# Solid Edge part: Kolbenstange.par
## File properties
Username: ahadarics
Dokumentum tartalom típus: 0
Author: ahadarics
Last saved by: ahadarics
Revision: 79
Sűrűség: 0,000 kg/m^3
Pontosság: 0,990
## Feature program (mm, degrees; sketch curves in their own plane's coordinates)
base feature "unnamed BaseFeature 1"
sketch for "unnamed Protrusion 1" plane through (90.5, 0, 0) normal (1, 0, 0) x-axis (0, 1, 0)
  circle centre (0, 0) radius 50
extrude "unnamed Protrusion 1" add finite 28 along -normal
thread "unnamed Thread 1"
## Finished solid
Body 1: solid body, 17 faces, 23 edges, 8 vertices.
  Faces by surface: plane 8, cylinder 4, torus 3, cone 2
  Edges by curve: circle 13, line 6, ellipse 2, intersection 2
Bounding box of the edges (mm; curved faces can reach further): 105.500 x 100.000 x 100.000, from (-15, -50, -50) to (90.5, 50, 50).
Cylindrical faces by radius (mm): R7 x1, R8 x1, R12.5 x1, R50 x1
Conical faces (half-angle, radius in mm at the cone's reference point): 20 deg R7.4 x1, 60 deg R7.6 x1
Toroidal faces (ring radius, tube radius in mm): R7.4 r0.4 x2, R10.7 r1.8 x1
Planar faces by outward normal: +x 1, +z 1, -x 3, -z 1, oblique 2
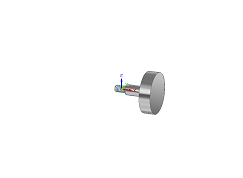
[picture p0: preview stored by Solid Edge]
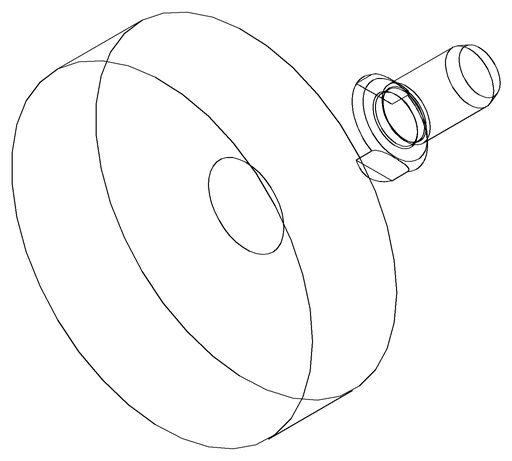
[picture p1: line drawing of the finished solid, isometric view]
